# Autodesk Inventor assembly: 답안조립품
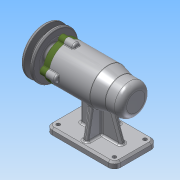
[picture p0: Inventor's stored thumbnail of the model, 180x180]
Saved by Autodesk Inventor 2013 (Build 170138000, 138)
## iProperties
Created: 2019-07
Part Number: 답안조립품
Document SubType Name: Assembly
Designer: Administrator
Author: Administrator
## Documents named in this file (12)
- C:\Users\Administrator\Desktop\490704V1047\답안조립품.iam
- C:\Users\Administrator\Desktop\490704V1047\본체.ipt
- C:\Users\Administrator\Desktop\490704V1047\커버.ipt
- C:\Users\Administrator\Desktop\490704V1047\오일 실.ipt
- C:\Users\Administrator\Desktop\490704V1047\베어링 6004.ipt
- C:\Users\Administrator\Desktop\490704V1047\축.ipt
- C:\Users\Administrator\Desktop\490704V1047\어댑터슬리브.ipt
- C:\Users\Administrator\Desktop\490704V1047\베어링 51202.ipt
- C:\Users\Administrator\Desktop\490704V1047\키 5 x 5 x 16.ipt
- C:\Users\Administrator\Desktop\490704V1047\V벨트풀리.ipt
- C:\Users\Administrator\Desktop\490704V1047\볼트 M4.ipt
- C:\Users\Administrator\Desktop\490704V1047\멈춤나사 M3.ipt
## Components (1 placed, 1 different names)
1. V벨트풀리:1 — 각도:2, 플러쉬:2
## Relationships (2: Angle 1, Flush 1)
- 각도:2 [Angle]: V벨트풀리:1
- 플러쉬:2 [Flush]: V벨트풀리:1
